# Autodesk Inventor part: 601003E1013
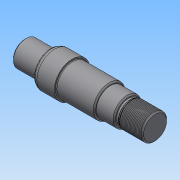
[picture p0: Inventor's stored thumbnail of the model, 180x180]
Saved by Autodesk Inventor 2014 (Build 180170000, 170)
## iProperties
Created: 2020-10
Part Number: 601003E1013
Material: 일반
Document SubType Name: Modeling
Designer: NET
Density: 1 g/cm^3
Appearance: 기본값
Author: NET
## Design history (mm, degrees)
sketch "스케치1"
  geometry: L1 (-84.656, 0)-(84.656, 0); L2 (-52, 0)-(-52, 10); L3 (-52, 10)-(-32, 10); L4 (-32, 10)-(-32, 14); L5 (-32, 14)-(-15, 14); L6 (-15, 14)-(-15, 12.5); L7 (-15, 12.5)-(15, 12.5); L8 (15, 12.5)-(15, 11); L9 (15, 11)-(29, 11); L10 (29, 11)-(29, 9.2); L11 (29, 9.2)-(30.6, 9.2); L12 (30.6, 9.2)-(31.986, 10); L13 (31.986, 10)-(50, 10); L14 (50, 10)-(50, 0); 3 further points
  constraints: 28 end point, 9 parallel, 2 coincident, 2 midpoint, 2 perpendicular, 2 point on line, 1 collinear, 1 horizontal, 1 vertical alignment
  dimensions: "d0" = 20 diameter of L3 L1; "d1" = 20 distance of L2.end L3.end; "d2" = 28 diameter of L5 L1; "d3" = 17 distance of L4.end L5.end; "d4" = 25 diameter of L7 L1; "d5" = 30 distance of L6.end L7.end; "d6" = 22 diameter of L9 L1; "d7" = 14 distance of L8.end L9.end; "d8" = 20 diameter of L13 L1; "d9" = 21 distance between parallel lines of L14 L10; "d10" = 1.6 distance of L10.end L11.end; "d11" = 18.4 diameter of L11 L1; "d12" = 150 deg angle of L11 L12
revolve "회전1" sketch "스케치1" stored, may be unused: angle "d13" = 90 deg
chamfer "모따기1" distance "d14" = 1; stored, may be unused: second distance "d15" = 2, angle "d16" = 45 deg
fillet "모깎기1" dims "d17" = 0.6
node "작업 평면1"
sketch "스케치2"
  geometry: L1 (10.729, 0)-(-1, 0); L2 (10, -3)-(-1, -3); L3 (-1, 3)-(10, 3); L4 (-10, 14)-(-10, -14) reference; L5 (10, 9)-(10, -9) reference; A1 r 3 centre (-1, 0) between (-1, 3) and (-1, -3); 3 further points
  constraints: 8 end point, 3 point on circle, 2 horizontal alignment, 2 point on line, 2 tangent, 1 centre point, 1 horizontal, 1 midpoint, 1 parallel
  dimensions: "d18" = 3 radius of A1; "d19" = 6 distance from line of point (-4, 0) L4
extrude "돌출1" cut sketch "스케치2" distance "d20" = 3.5; taper "d21" = 0 deg
fillet "모깎기2" dims "d22" = 0.6
chamfer "모따기2" distance "d23" = 1.35; stored, may be unused: second distance "d24" = 2, angle "d25" = 60 deg
fillet "모깎기3" dims "d26" = 4
fillet "모깎기4" dims "d27" = 1
feature "스레드1" dims "d28" = 10, "d29" = 0
chamfer "모따기3" distance "d30" = 1; stored, may be unused: second distance "d31" = 2, angle "d32" = 45 deg
chamfer "모따기4" distance "d33" = 1; stored, may be unused: second distance "d34" = 2, angle "d35" = 45 deg
node "솔리드1"
